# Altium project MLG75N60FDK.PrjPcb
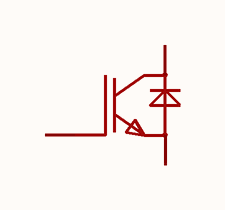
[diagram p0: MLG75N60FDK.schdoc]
1 sheet, 1 parts. Net scope: global (net labels, ports and power ports of the same name join across sheets).

## Sheet MLG75N60FDK.schdoc
size 127 x 101 mm

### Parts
Q?  mlg75n60fdk  [TO-247-3_L15.8-W5.0-P5.44-L]  (value not drawn)

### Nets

Not connected (* = marked no-connect by the designer): Q? 1(G) 2(C) 3(E)

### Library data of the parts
Q? = mlg75n60fdk: IGBT类型:FS(场截止);耗散功率(Pd):468W;集射极击穿电压(Vces):600V;集电极电流(Ic):150A;; Manufacturer: minos(迈诺斯); AddInBom: yes; ModelId: 2dc33f6e48bd44aa838c2b9e2b85eb16; ModelTransform: 622.04631,185.078,0,0,0,0,-0.003,13.778,-196.85; Pd - Power Dissipation: 468W; Collector-Emitter Breakdown Voltage (Vces): 600V; Current - Collector(Ic): 150A; Current - Collector Pulsed (Icm): 240A; Vce Saturation(VCE(sat)): 2.4V@75A,15V; Gate-Emitter Threshold Voltage (Vge(th)@Ic): 4.7V@1mA; Gate Charge(Qg): 156nC@520V; Input Capacitance(Cies): 3.979nF@25V; Output Capacitance(Coes): 187pF; Reverse Transfer Capacitance (Cres): 36pF; Td(on): 29ns; Td(off): 110ns; Turn-On Energy (Eon): 1.25mJ; Switching Energy(Eoff): 1.1mJ; Reverse Recovery Time(trr): 36ns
